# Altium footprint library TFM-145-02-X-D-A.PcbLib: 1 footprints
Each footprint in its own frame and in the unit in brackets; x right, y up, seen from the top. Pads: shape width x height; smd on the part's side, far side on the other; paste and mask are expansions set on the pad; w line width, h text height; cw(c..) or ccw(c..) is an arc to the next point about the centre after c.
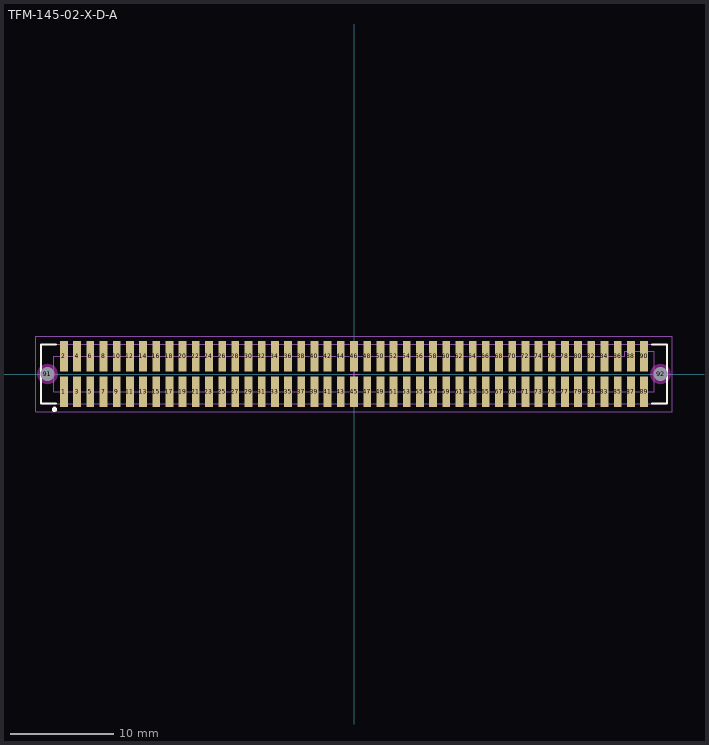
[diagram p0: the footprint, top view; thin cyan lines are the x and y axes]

## TFM-145-02-X-D-A [mm] "1.27mm pitch, 90 pin, terminal strip; w/alignment pins, SMT"
height 5.72
pads (92):
  rect 0.75x2.9 smd mask+0: 1(-27.94,-1.714) 2(-27.94,1.714) 3(-26.67,-1.714) 4(-26.67,1.714) 5(-25.4,-1.714) 6(-25.4,1.714) 7(-24.13,-1.714) 8(-24.13,1.714) 9(-22.86,-1.714) 10(-22.86,1.714) 11(-21.59,-1.714) 12(-21.59,1.714) 13(-20.32,-1.714) 14(-20.32,1.714) 15(-19.05,-1.714) 16(-19.05,1.714) 17(-17.78,-1.714) 18(-17.78,1.714) 19(-16.51,-1.714) 20(-16.51,1.714) 21(-15.24,-1.714) 22(-15.24,1.714) 23(-13.97,-1.714) 24(-13.97,1.714) 25(-12.7,-1.714) 26(-12.7,1.714) 27(-11.43,-1.714) 28(-11.43,1.714) 29(-10.16,-1.714) 30(-10.16,1.714) 31(-8.89,-1.714) 32(-8.89,1.714) 33(-7.62,-1.714) 34(-7.62,1.714) 35(-6.35,-1.714) 36(-6.35,1.714) 37(-5.08,-1.714) 38(-5.08,1.714) 39(-3.81,-1.714) 40(-3.81,1.714) 41(-2.54,-1.714) 42(-2.54,1.714) 43(-1.27,-1.714) 44(-1.27,1.714) 45(0,-1.714) 46(0,1.714) 47(1.27,-1.714) 48(1.27,1.714) 49(2.54,-1.714) 50(2.54,1.714) 51(3.81,-1.714) 52(3.81,1.714) 53(5.08,-1.714) 54(5.08,1.714) 55(6.35,-1.714) 56(6.35,1.714) 57(7.62,-1.714) 58(7.62,1.714) 59(8.89,-1.714) 60(8.89,1.714) 61(10.16,-1.714) 62(10.16,1.714) 63(11.43,-1.714) 64(11.43,1.714) 65(12.7,-1.714) 66(12.7,1.714) 67(13.97,-1.714) 68(13.97,1.714) 69(15.24,-1.714) 70(15.24,1.714) 71(16.51,-1.714) 72(16.51,1.714) 73(17.78,-1.714) 74(17.78,1.714) 75(19.05,-1.714) 76(19.05,1.714) 77(20.32,-1.714) 78(20.32,1.714) 79(21.59,-1.714) 80(21.59,1.714) 81(22.86,-1.714) 82(22.86,1.714) 83(24.13,-1.714) 84(24.13,1.714) 85(25.4,-1.714) 86(25.4,1.714) 87(26.67,-1.714) 88(26.67,1.714) 89(27.94,-1.714) 90(27.94,1.714)
  round 1 hole 1.35 unplated mask+0: 91(-29.527,0) 92(29.527,0)
Top Overlay:
  circle w0.25: c-28.85,-3.4 r0.125
  lines w0.2: -28.7,-2.85 -30.15,-2.85 -30.15,2.85 -28.7,2.85 ; 28.7,-2.85 30.15,-2.85 30.15,2.85 28.7,2.85
Keep-Out Layer:
  pour cut-out: 30.511,0 30.478,0.255 30.379,0.492 30.223,0.695 30.019,0.852 29.782,0.95 29.528,0.983 29.273,0.95 29.036,0.852 28.832,0.695 28.676,0.492 28.578,0.255 28.544,0 28.578,-0.255 28.676,-0.492 28.832,-0.695 29.036,-0.852 29.273,-0.95 29.528,-0.983 29.782,-0.95 30.019,-0.852 30.223,-0.695 30.379,-0.492 30.478,-0.255
  pour cut-out: -28.544,0 -28.578,0.255 -28.676,0.492 -28.832,0.695 -29.036,0.852 -29.273,0.95 -29.528,0.983 -29.782,0.95 -30.019,0.852 -30.223,0.695 -30.379,0.492 -30.478,0.255 -30.511,0 -30.478,-0.255 -30.379,-0.492 -30.223,-0.695 -30.019,-0.852 -29.782,-0.95 -29.528,-0.983 -29.273,-0.95 -29.036,-0.852 -28.832,-0.695 -28.676,-0.492 -28.578,-0.255
Mechanical 12:
  lines w0.001: -30.15,-2.85 -30.15,2.85 30.15,2.85 30.15,-2.85 -30.15,-2.85 ; -28.9,-1.7 -28.9,1.7 26.1,1.7 26.1,2.2 28.9,2.2 28.9,-1.7 -28.9,-1.7
Mechanical 13:
  circle w0.1: c-28.837,-3.379 r0.127
  lines w0.1: -30.15,-2.85 -30.15,2.85 30.15,2.85 30.15,-2.85 -30.15,-2.85 ; -28.9,-1.7 -28.9,1.7 26.1,1.7 26.1,2.2 28.9,2.2 28.9,-1.7 -28.9,-1.7
  text ".Designator" at 0,-0.127 h1.52
Mechanical 15:
  lines w0.05: -0.5,0 0.5,0 ; 0,-0.5 0,0.5 ; -30.65,-3.65 -30.65,3.65 30.65,3.65 30.65,-3.65 -30.65,-3.65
